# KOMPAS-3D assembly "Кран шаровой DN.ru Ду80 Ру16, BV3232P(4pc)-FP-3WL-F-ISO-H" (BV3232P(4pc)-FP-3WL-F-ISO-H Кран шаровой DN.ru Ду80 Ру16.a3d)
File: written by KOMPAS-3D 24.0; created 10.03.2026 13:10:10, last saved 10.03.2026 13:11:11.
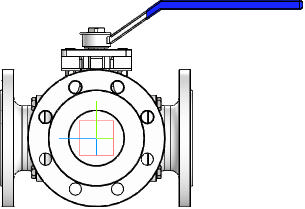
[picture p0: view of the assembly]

Document properties: Автор: R2D2; Полное имя файла: E:\Работа\Зайцев\BV3232P(4pc)-FP-3WL-F-ISO-H Кран шаровой DN.ru Ду15-100 Ру16\DN80\исходные материалы\BV3232P(4pc)-FP-3WL-F-ISO-H Кран шаровой DN.ru Ду80 Ру16.a3d

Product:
- Component [assembly]: Сборка1  | qty 1  | Масса: 39.43139; Автор: R2D2; source file: dn80_3d_step.a3d
- Part/product: Кран шаровой DN.ru Ду80 Ру16  | designation BV3232P(4pc)-FP-3WL-F-ISO-H
    Масса: 39.1
    Раздел спецификации: Прочие изделия
    Примечание: D160-36362

Referenced files in E:\Работа\Зайцев\BV3232P(4pc)-FP-3WL-F-ISO-H Кран шаровой DN.ru Ду15-100 Ру16\DN80\исходные материалы\: dn80_3d_step.a3d
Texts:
  BV3232P(4pc)-FP-3WL-F-ISO-H
  Сборка1 Сборка1
  Ось Z.Начало координат
  Ось Y.Начало координат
